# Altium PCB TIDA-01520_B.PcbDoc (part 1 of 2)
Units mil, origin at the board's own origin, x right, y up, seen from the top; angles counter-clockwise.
Board outline 2952.76 x 2362.2 mil, 2 copper layers (Top Layer, Bottom Layer), stack 62 mil thick; 118 components, 52 nets, 283 pads, 133 vias.
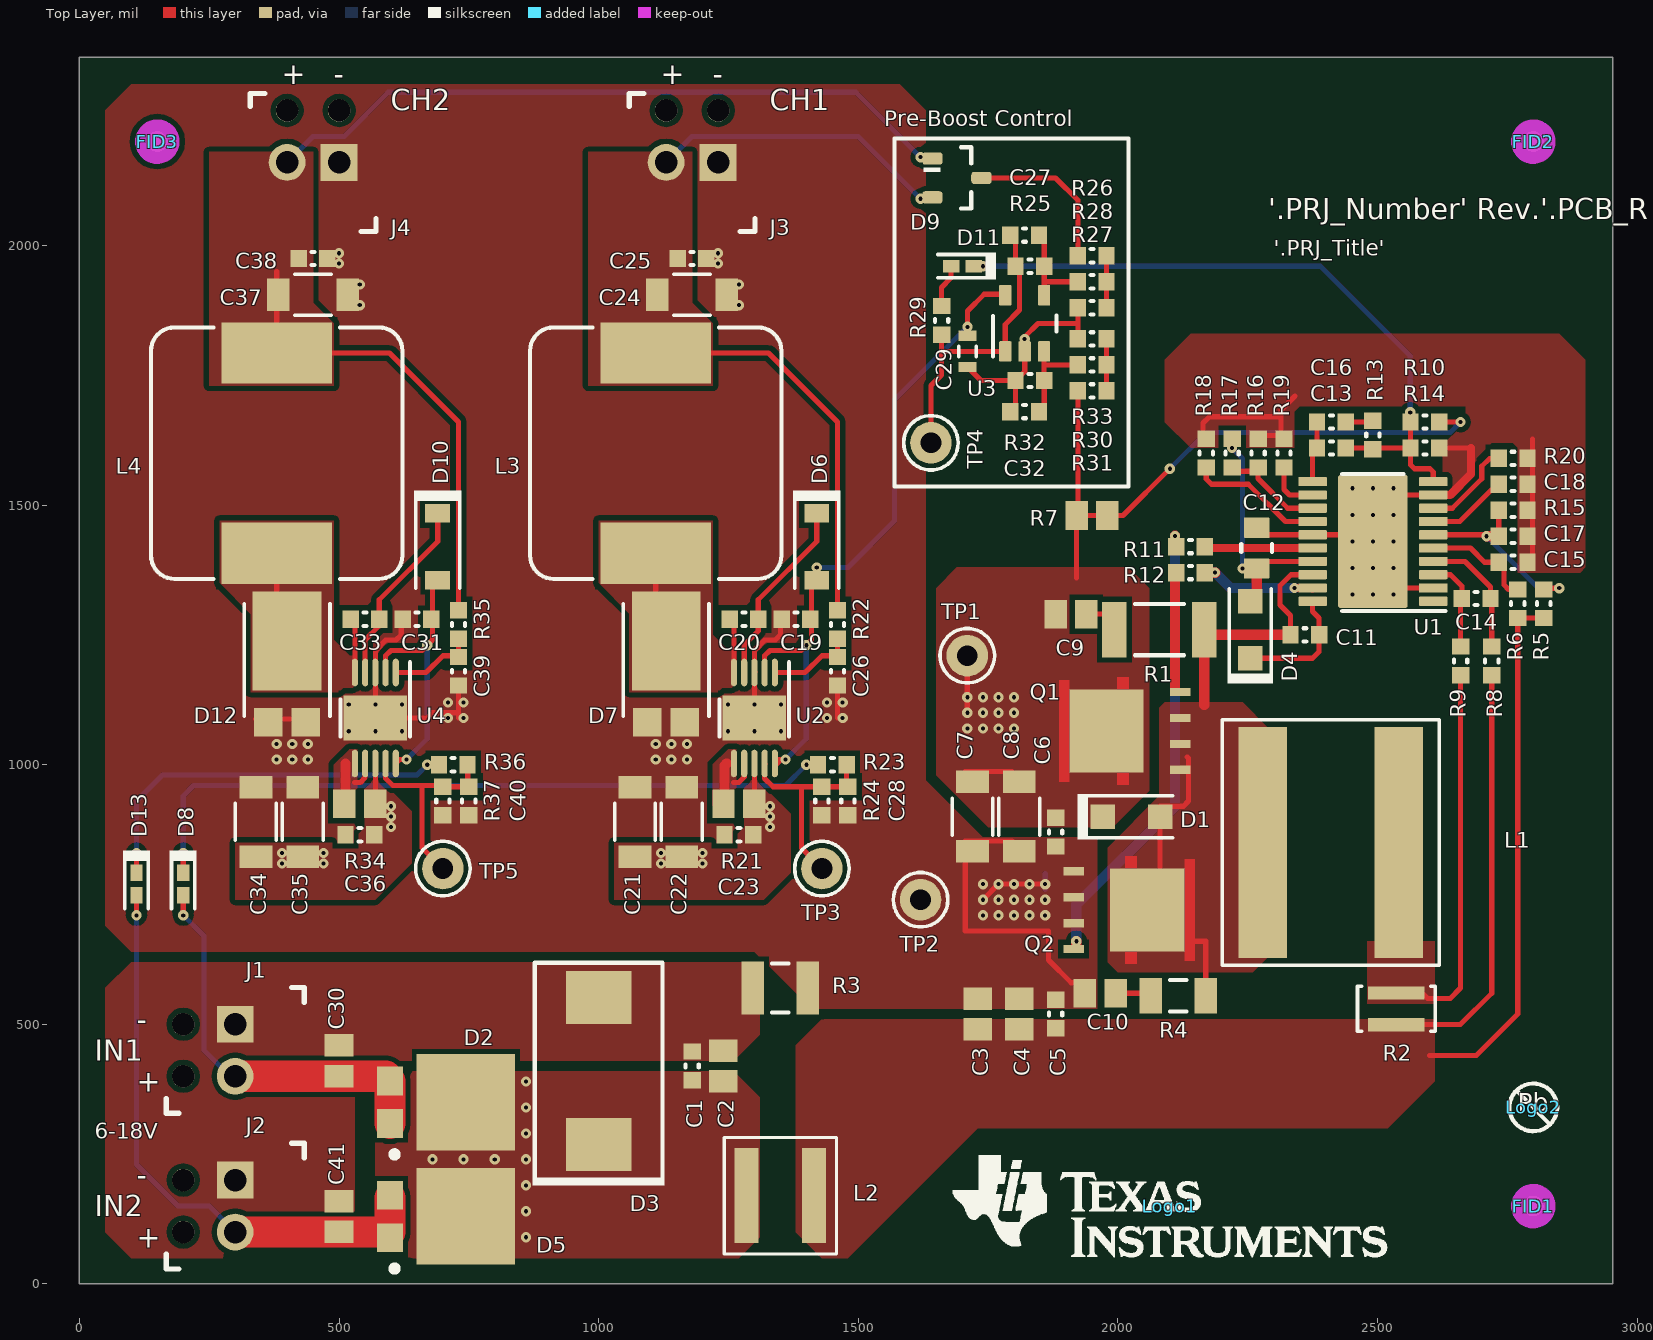
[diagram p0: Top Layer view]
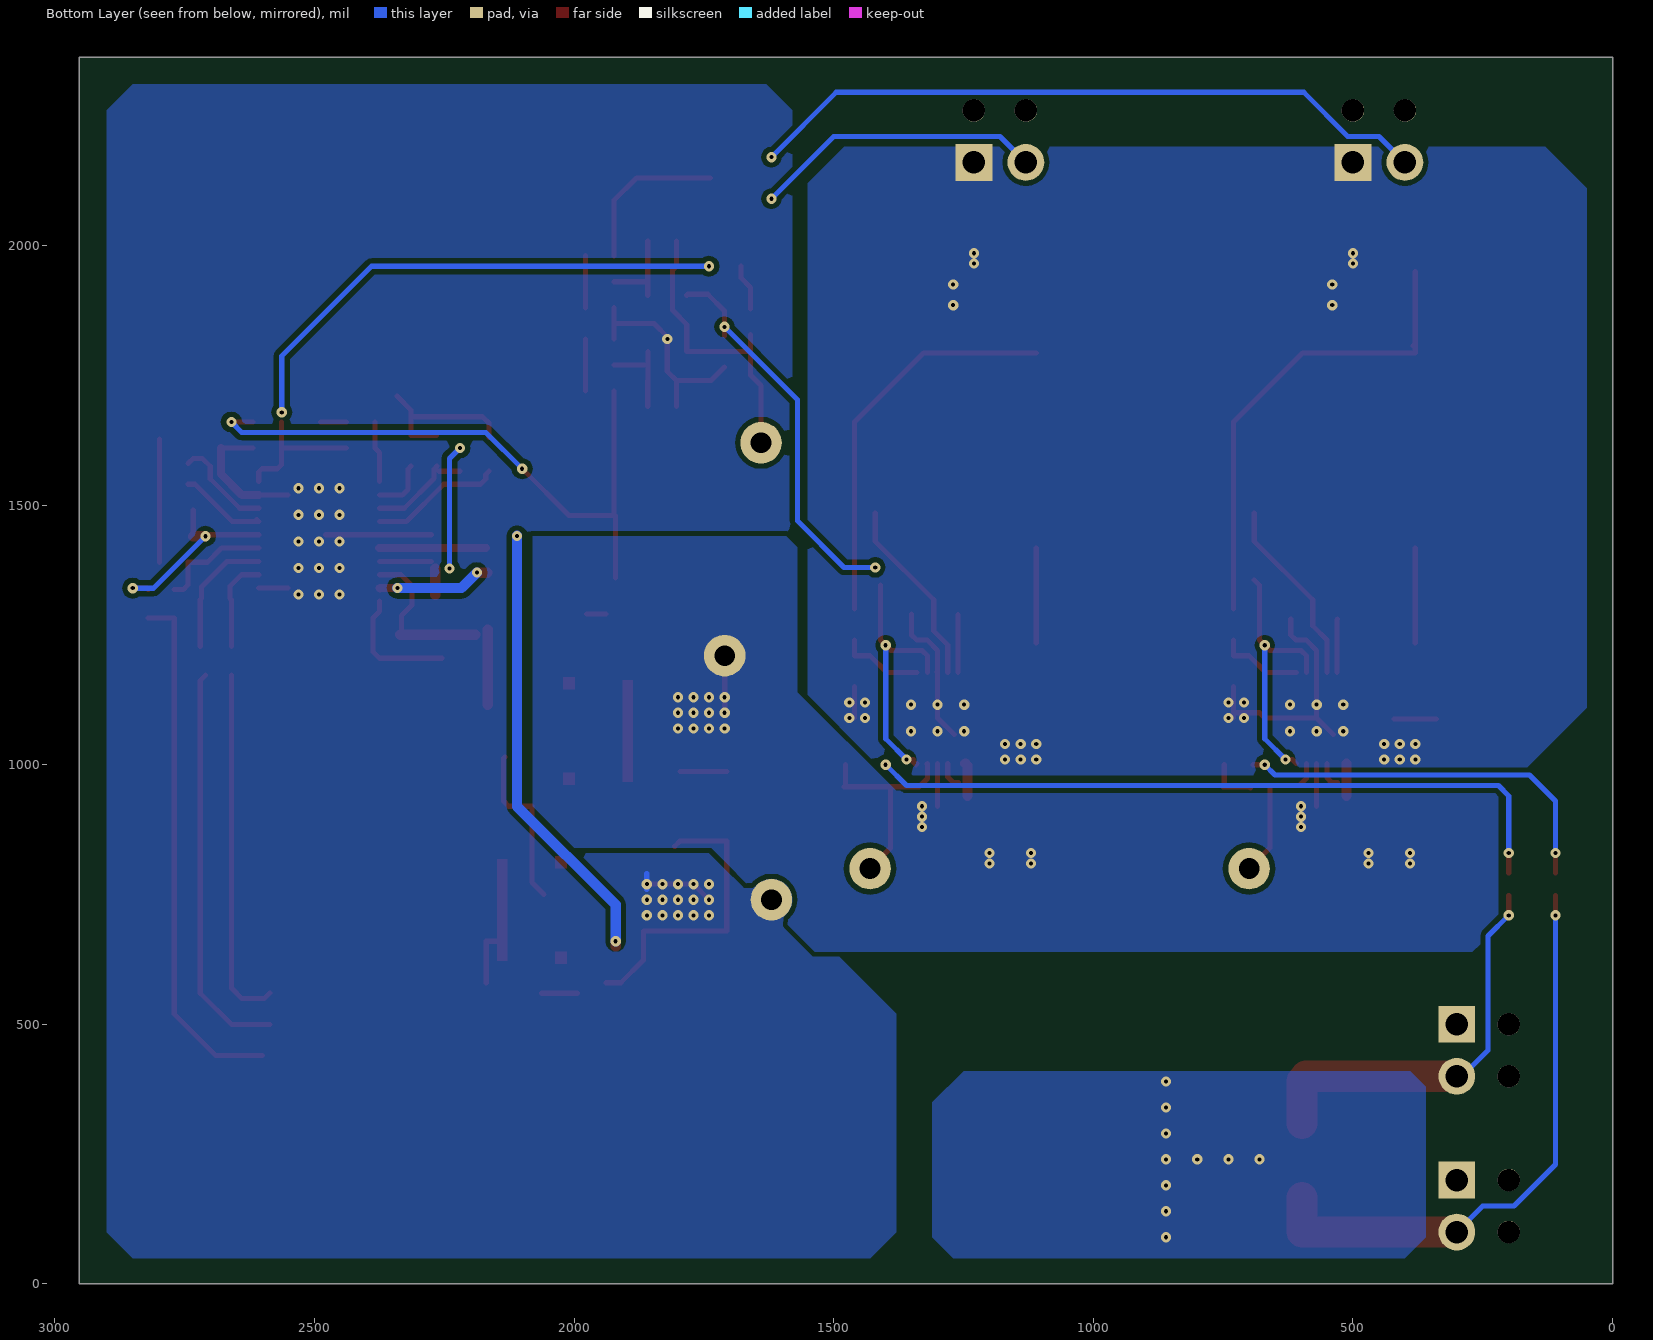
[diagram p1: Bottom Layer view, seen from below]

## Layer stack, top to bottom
Top Solder: solder mask 0.4, Solder Resist, Dk 3.5
Top Layer: signal copper 1.4
Dielectric1: core 59.2, FR-4, Dk 4.8
Bottom Layer: signal copper 1.4
Bottom Solder: solder mask 0.4, Solder Resist, Dk 3.5

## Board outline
0,0 2952.76,0 2952.76,2362.2 0,2362.2

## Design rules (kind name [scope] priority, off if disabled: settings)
AcuteAngle [All] p1: minimum=4.50000000000000E+0001 checktracksonly=FALSE
AssemblyTestPointUsage [All] p1: valid=2
BoardOutlineClearance BoardOutlineClearance_MountingHoles [OnCopper and InComponentClass('Mounting Holes')] p1: gap=40
BoardOutlineClearance BoardOutlineClearance_Poly [OnCopper and IsPoly] p2: gap=25
BoardOutlineClearance [OnCopper and Not InComponentClass('Logo') and not InComponentClass('FiducialMark') and not InRegion(1000,500,4000,800) and not InPoly] p3: gap=35
Clearance Clearance_Keepouts [((IsTrack Or IsArc) And Not InPoly) And IsFree and IsKeepOut vs ((IsTrack Or IsArc) And Not InPoly) And IsFree and IsKeepOut] p1: gap=0
Clearance Clearance_Poly [InPolygon] p2: gap=10
Clearance [All] p3: gap=7.87
ComponentClearance ComponentClearance_MountingHoles_FiducialMarks [InComponentClass('Mounting Holes') vs InComponentClass('FiducialMark')] p1: gap=50 collisioncheckmode=3 verticalgap=10 showdistances=FALSE
ComponentClearance ComponentClearance_Shunt [InComponentClass('Header') vs InComponentClass('Shunt')] p2: gap=0 collisioncheckmode=3 verticalgap=0 showdistances=FALSE
ComponentClearance ComponentClearance_Logo [InComponentClass('Logo')] p3: gap=50 collisioncheckmode=3 verticalgap=10 showdistances=FALSE
ComponentClearance ComponentClearance_ScrewToNut [(HasFootprint('NY PMS 440 0025 PH')) vs (HasFootprint('Keystone_1902C'))] p4: gap=5 collisioncheckmode=3 verticalgap=10 showdistances=FALSE
ComponentClearance ComponentClearance_MountingHoles [InComponentClass('Mounting Holes')] p5: gap=180 collisioncheckmode=3 verticalgap=100000 showdistances=FALSE
ComponentClearance ComponentClearance_SmallPassives [HasFootprint('0201*') or HasFootprint('0402*') or HasFootprint('0508') or HasFootprint('0603*') or HasFootprint('0612') or HasFootprint('0805*') or HasFootprint('0815*') or HasFootprint('0830*') or HasFootprint('1206*') or HasFootprint('1210*') or HasFootprint('1808*') or HasFootprint('1812*') or HasFootprint('1825*') or HasFootprint('2010*') or HasFootprint('2220*') or HasFootprint('2225*') or HasFootprint('2512*') or HasFootprint('2728*') or HasFootprint('3518*') vs HasFootprint('0201*') or HasFootprint('0402*') or HasFootprint('0508') or HasFootprint('0603*') or HasFootprint('0612') or HasFootprint('0805*') or HasFootprint('0815*') or HasFootprint('0830*') or HasFootprint('1206*') or HasFootprint('1210*') or HasFootprint('1808*') or HasFootprint('1812*') or HasFootprint('1825*') or HasFootprint('2010*') or HasFootprint('2220*') or HasFootprint('2225*') or HasFootprint('2512*') or HasFootprint('2728*') or HasFootprint('3518*')] p6: gap=12 collisioncheckmode=3 verticalgap=10 showdistances=FALSE
ComponentClearance ComponentClearance_THtoSMT [IsThruComponent vs IsSMTComponent] p7: gap=40 collisioncheckmode=3 verticalgap=30 showdistances=FALSE
ComponentClearance ComponentClearance_THtoTH [IsThruComponent vs IsThruComponent] p8: gap=30 collisioncheckmode=3 verticalgap=30 showdistances=FALSE
ComponentClearance [All] p9: gap=30 collisioncheckmode=3 verticalgap=10 showdistances=FALSE
DiffPairsRouting [All] p1: maxlimit=100 minlimit=10 mostfreqgap=10 toplayer_minwidth=15 toplayer_maxwidth=15 toplayer_prefwidth=15 bottomlayer_minwidth=15 bottomlayer_maxwidth=15 bottomlayer_prefwidth=15 maxuncoupledlength=1000
FabricationTestPointUsage TestPointUsage [All] p1: valid=2 allowmultiple=FALSE
FabricationTestpoint Testpoint [All] p1: side=3 testpointundercomponent=TRUE minsize=40 maxsize=100 preferedsize=60 minholesize=0 maxholesize=40 preferedholesize=32 testpointgrid=1 allowsidetop=TRUE allowsidebottom=TRUE usegrid=TRUE gridtolerance=0.01
FanoutControl Fanout_LCC [IsLCC] p1: bgadir=Out bgaviamode=Centered fanoutstyle=Auto fanoutdirection=Alternating viagrid=1 // Fanout_LCC (Default Rule)
FanoutControl Fanout_BGA [IsBGA] p2: bgadir=Out bgaviamode=Centered fanoutstyle=Auto fanoutdirection=Alternating viagrid=1 // Fanout_BGA (Default Rule)
FanoutControl Fanout_Default [All] p4: bgadir=Out bgaviamode=Centered fanoutstyle=Auto fanoutdirection=Alternating viagrid=1 // Fanout_Default (Default Rule)
FanoutControl Fanout_Small [(CompPinCount < 5)] p5: bgadir=Out bgaviamode=Centered fanoutstyle=Auto fanoutdirection=OutThenIn viagrid=1 // Fanout_Small (Default Rule)
HoleSize [All] p1: absolutevalues=TRUE maxlimit=251 minlimit=7.87 maxpercent=80.000 minpercent=20.000
MinimumAnnularRing MinimumAnnularRing_ThermalPadVias [IsVia and InAnyComponent] p1: minimumring=5.91
MinimumAnnularRing [All] p2: minimumring=5.91
MinimumSolderMaskSliver MinimumSolderMaskSliver_Logo [InComponentClass('Logo') vs InComponentClass('Logo')] p1: minsoldermaskwidth=0.7
MinimumSolderMaskSliver [All] p2: minsoldermaskwidth=3.94
PlaneConnect [All] p1: planeconnectstyle=Relief reliefexpansion=10 reliefentries=4 reliefconductorwidth=10 reliefairgap=10
PolygonConnect [All] p1: connectstyle=Direct reliefconductorwidth=10 reliefentries=4 polygonreliefangle="90 Angle" airgapwidth=10
RoutingVias ThermalPadVias [IsVia and InAnyComponent] p1: holewidth=7.87 width=19.68 viastyle="Through Hole" minholewidth=7.87 minwidth=19.68 maxholewidth=12.99 maxwidth=23.62
RoutingVias [All] p2: holewidth=16 width=34 viastyle="Through Hole" minholewidth=7.87 minwidth=19.68 maxholewidth=40 maxwidth=65
SilkToBoardRegionClearance [Not ((IsComment or IsDesignator) And (Hide <> 'False')) and not InRegion(1000,500,4000,800)] p1:
SilkToSilkClearance SilkToSilkClearance_Pb-FreeLogo [(HasFootprint('Pb-Free_Overlay_Medium') OR HasFootprint('Pb-Free_Overlay_Small')) vs (HasFootprint('Pb-Free_Overlay_Medium') OR HasFootprint('Pb-Free_Overlay_Small'))] p1: silktosilkclearance=0
SilkToSilkClearance [All] p2: silktosilkclearance=4
SilkToSolderMaskClearance SilkToSolderMaskClearance_D4 [InComponent('D4') or InComponent('D1')  or InComponent('D2') or InComponent('D8') or InComponent('D13') or InComponent('D3')] p1: minsilkscreentomaskgap=3.29 clearancetoexposedcopper=TRUE
SilkToSolderMaskClearance SilkToComponentPadClearance [(IsPad or IsFill or IsRegion) and InAnycomponent] p2: minsilkscreentomaskgap=5 clearancetoexposedcopper=TRUE
SilkToSolderMaskClearance "Silk to Solder Mask Opening" [All] p3: minsilkscreentomaskgap=4 clearancetoexposedcopper=FALSE
SolderMaskExpansion [All] p1: expansion=1.97
Width [All] p1: maxlimit=100 minlimit=6 preferedwidth=10 checkconnectedcopper=TRUE
15 further rules are at their usual default settings.

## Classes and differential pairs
component class Logo: Logo1
component class TIDA-01520_B_Hardware: FID1 FID2 FID3 Logo1 Logo2 ZZ1 ZZ2 ZZ3
component class FiducialMark: FID1 FID2 FID3
component class AssemblyNote: ZZ1 ZZ2 ZZ3
component class TIDA-01520_B: C1 C2 C3 C4 C5 C6 C7 C8 C9 C10 C11 C12 C13 C14 C15 C16 C17 C18 C19 C20 C21 C22 C23 C24 C25 C26 C27 C28 C29 C30 C31 C32 C33 C34 C35 C36 C37 C38 C39 C40 C41 D1 D2 D3 D4 D5 D6 D7 D8 D9 D10 D11 D12 D13 J1 J2 J3 J4 L1 L2 L3 L4 L22 Q1 Q2 R1 R2 R3 R4 R5 R6 R7 R8 R9 R10 R11 R12 R13 R14 R15 R16 R17 R18 R19 R20 R21 R22 R23 R24 R25 R26 R27 R28 R29 R30 R31 R32 R33 R34 R35 R36 R37 TP1 TP2 TP3 TP4 TP5 U1 U2 U3 U4

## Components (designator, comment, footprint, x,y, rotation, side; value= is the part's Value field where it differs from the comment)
C1 "CGA3E2X7R1H104K080AA" 0603L 1180,420 r90 top
C2 "CGA4J3X5R1H475M125AB" 0805L 1240,420 r90 top
C3 "CGA4J3X5R1H475M125AB" 0805L 1730,520 r90 top
C4 "CGA4J3X5R1H475M125AB" 0805L 1810,520 r90 top
C5 "CGA3E2X7R2A102K080AA" 0603L 1880,520 r90 top
C6 "CGA3E3X7S2A104K080AB" 0603L 1880,870 r270 top
C7 "CGA5L3X7S2A225K160AB" 1206_180 1720,900 r270 top
C8 "CGA5L3X7S2A225K160AB" 1206_180 1810,900 r270 top
C9 "GRM216R71E681KA01D" 0805L 1909.53,1290 r0 top
C10 "GRM2165C2A681JA01D" 0805L 1966.14,560 r180 top
C11 "CGA3E2X7R1H104K080AA" 0603L 2360,1250 r180 top
C12 "GCM21BR71C475KA73L" 0805_HV1 2267.14,1417.2 r270 top
C13 "CGA3E2X7R2A102K080AA" 0603L 2411.14,1610 r0 top
C14 "CGA3E2NP01H101J080AA" 0603L 2690,1320 r180 top
C15 "CGA3E3X7R1H474K080AE" 0603L 2761.14,1390 r0 top
C16 "CGA3E2X7R1H104K080AA" 0603L 2411.14,1660 r0 top
C17 "CGA3E2NP01H101J080AA" 0603L 2761.14,1440 r0 top
C18 "CGA3E3X8R1E224K080AB" 0603L 2761.14,1540 r0 top
C19 "GRM188R60J106ME84" 0603L 1380,1280 r180 top
C20 "CGA3E1X7R1V105K080AC" 0603L 1280,1280 r180 top
C21 "CGA5L3X7S2A225K160AB" 1206_180 1070,890 r90 top
C22 "CGA5L3X7S2A225K160AB" 1206_180 1160,890 r90 top
C23 "CGA3E3X7S2A104K080AB" 0603L 1270,865 r180 top
C24 "CGA5L3X7S2A225K160AB" 1206_180 1180,1905 r0 top
C25 "CGA3E3X7S2A104K080AB" 0603L 1180,1975 r0 top
C26 "GRM1885C1H471JA01D" 0603L 1460,1180 r270 top
C27 "CGA3E2X7R1H473K080AA" 0603L 1820.47,2020 r0 top
C28 "CGA3E2X7R1H104K080AA" 0603L 1480,930 r270 top
C29 "CGA3E2X7R1H104K080AA" 0603S 1710.47,1795.86 r270 top
C30 "CGA4J3X5R1H475M125AB" 0805L 500,430 r90 top
C31 "GRM188R60J106ME84" 0603L 650,1280 r180 top
C32 "CGA3E2X7R1H473K080AA" 0603L 1820.47,1680 r180 top
C33 "CGA3E1X7R1V105K080AC" 0603L 550,1280 r180 top
C34 "CGA5L3X7S2A225K160AB" 1206_180 340,890 r90 top
C35 "CGA5L3X7S2A225K160AB" 1206_180 430,890 r90 top
C36 "CGA3E3X7S2A104K080AB" 0603L 540,865 r180 top
C37 "CGA5L3X7S2A225K160AB" 1206_180 450,1905 r0 top
C38 "CGA3E3X7S2A104K080AB" 0603L 450,1975 r0 top
C39 "GRM1885C1H471JA01D" 0603L 730,1180 r270 top
C40 "CGA3E2X7R1H104K080AA" 0603L 750,930 r270 top
C41 "CGA4J3X5R1H475M125AB" 0805L 500,130 r90 top
D1 "PMEG6010CEH,115" SOD-123F 2026.14,900 r0 top
D2 "V12P10-M3/86A" TO-277A 670,350 r90 top
D3 "TPSMD26A" SMC_265 1000,410 r90 top
D4 "PMEG6010CEH,115" SOD-123F 2255,1260 r90 top
D5 "V12P10-M3/86A" TO-277A 670,130 r90 top
D6 "MMSD4148T1G" SOD-123 1420,1420 r270 top
D7 "PDS3100Q-13" PowerDI5 1130,1160 r90 top
D8 "RB520S30,115" SOD-523 200,770 r270 top
D9 "BAS70-05-7-F" SOT-23 1690,2130 r0 top
D10 "MMSD4148T1G" SOD-123 690,1420 r270 top
D11 "RB520S30,115" SOD-523 1700.47,1960 r180 top
D12 "PDS3100Q-13" PowerDI5 400,1160 r90 top
D13 "RB520S30,115" SOD-523 110,770 r270 top
FID1 "Fiducial" Fiducial10-20 2800,150 r180 top
FID2 "Fiducial" Fiducial10-20 2800,2200 r180 top
FID3 "Fiducial" Fiducial10-20 150,2200 r180 top
J1 "1725656" CONN_1725656 300,450 r270 top
J2 "1725656" CONN_1725656 300,150 r270 top
J3 "1725656" CONN_1725656 1180,2160 r180 top
J4 "1725656" CONN_1725656 450,2160 r180 top
L1 "XAL1010-153MEB" XAL1010 2410,850 r180 top
L2 "XAL5030-222MEB" XAL5030 1350,170 r0 top
L3 "784771470" WE-PDA_1260 1110,1600 r180 top
L4 "784771470" WE-PDA_1260 380,1600 r180 top
Logo1 "Texas Instruments" TI_Stacked_Overlay_Small 2100,150 r0 top
Logo2 "Pb-Free Symbol" Pb-Free_Overlay_Small 2800,340 r0 top
Q1 "SQJA60EP" PowerPAK_SO-8L 2010,1065 r180 top
Q2 "SQJA60EP" PowerPAK_SO-8L 2025,720 r0 top
R1 "CRCW20106R80JNEF" 2010L 2080,1260 r180 top
R2 "PRL1632-R006-F-T1" 0612 2536.14,530 r90 top
R3 "CRCW12100000Z0EA" 1210L 1350,570 r0 top
R4 "PHP01206E10R0BST5" 1206L 2116.14,555 r0 top
R5 "CRCW0603100KJNEA" 0603L 2820,1310 r270 top
R6 "CRCW06033R30JNEA" 0603L 2770,1310 r270 top
R7 "CRCW080549R9FKEA" 0805L 1950,1480 r180 top
R8 "CRCW06031K00FKEA" 0603L 2720,1200 r270 top
R9 "CRCW06031K00FKEA" 0603L 2660,1200 r270 top
R10 "CRCW0603100KFKEA" 0603L 2591.14,1660 r0 top
R11 "CRCW060330R0JNEA" 0603L 2140,1420 r180 top
R12 "CRCW06030000Z0EA" 0603L 2140,1370 r180 top
R13 "CRCW06031K00FKEA" 0603L 2491.14,1635 r90 top
R14 "CRCW06032K74FKEA" 0603L 2591.14,1610 r0 top
R15 "CRCW060322K0JNEA" 0603L 2761.14,1490 r180 top
R16 "CRCW06030000Z0EA" 0603L 2270,1600 r90 top
R17 "CRCW06030000Z0EA" 0603L 2220,1600 r90 top
R18 "CRCW06030000Z0EA" 0603L 2170,1600 r270 top
R19 "CRCW060349K9FKEA" 0603L 2320,1600 r270 top
R20 "RC0603FR-0727KL" 0603L 2761.14,1590 r180 top
R21 "ERJ-6RQFR22V" 0805L 1270,925 r0 top
R22 "CRCW060310K0FKEA" 0603L 1460,1270 r90 top
R23 "CRCW06032K00FKEA" 0603L 1450,1000 r180 top
R24 "CRCW0603330RJNEA" 0603L 1430,930 r270 top
R25 "CRCW0603300KFKEA" 0603L 1830.47,1960 r180 top
R26 "RC0603FR-0718KL" 0603L 1950.47,1980 r180 top
R27 "CRCW06032K00FKEA" 0603L 1950.47,1880 r0 top
R28 "CRCW060310K0FKEA" 0603L 1950.47,1930 r180 top
R29 "CRCW060313K3FKEA" 0603L 1660.47,1855.86 r90 top
R30 "CRCW060310K0FKEA" 0603L 1950.47,1770 r180 top
R31 "RC0603FR-0722KL" 0603L 1950.47,1720 r180 top
R32 "CRCW0603300KFKEA" 0603L 1830.47,1740 r0 top
R33 "CRCW06032K00FKEA" 0603L 1950.47,1820 r0 top
R34 "ERJ-6RQFR22V" 0805L 540,925 r0 top
R35 "CRCW060310K0FKEA" 0603L 730,1270 r90 top
R36 "CRCW06032K00FKEA" 0603L 720,1000 r180 top
R37 "CRCW0603330RJNEA" 0603L 700,930 r270 top
TP1 "5001" Keystone5001 1710,1210 r90 top
TP2 "5001" Keystone5001 1620,740 r90 top
TP3 "5001" Keystone5001 1430,800 r90 top
TP4 "5001" Keystone5001 1640,1620 r90 top
TP5 "5001" Keystone5001 700,800 r90 top
U1 "LM5122QMHX/NOPB" PWP0020A_N 2491.14,1430 r180 top
U2 "TPS92515HVQDGQRQ1" DGQ0010E_N 1300,1090 r270 top
U3 "OPA348AQDBVRQ1" DBV0005A_N 1820.47,1850 r90 top
U4 "TPS92515HVQDGQRQ1" DGQ0010E_N 570,1090 r270 top
ZZ1 "These assemblies are ESD sensitive, ESD precautions shall be observed." AssemblyNote 0,2760 r0 top
ZZ2 "These assemblies must be clean and free from flux and all contaminants. Use of no clean flux is not acceptable." AssemblyNote 0,2662.2 r0 top
ZZ3 "These assemblies must comply with workmanship standards IPC-A-610 Class 2, unless otherwise specified." AssemblyNote 0,2562.2 r0 top

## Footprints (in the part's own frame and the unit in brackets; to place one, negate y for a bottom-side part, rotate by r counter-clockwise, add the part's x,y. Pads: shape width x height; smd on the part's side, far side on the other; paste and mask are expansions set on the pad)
0603L [mm] "0603 from SM-752 data"
  rect 0.8x0.85 smd: 1(-0.7,0) 2(0.7,0)
  silkscreen extent -0.07,-0.33 0.07,0.33, body extent -0.87,-0.47 0.87,0.47, height 1
0603S [mil]
  rect 20x35 smd: 1(-30,0) 2(30,0)
  silkscreen extent -10,-17 10,17, body extent -34,-19 34,19, height 39
0612 [mm] "Panasonic recommended land pattern, fb97d03ed01.pdf dated April 2008"
  rect 0.65x2.75 smd: 1(-0.775,0) 2(0.775,0)
  silkscreen extent -1.1,-1.9 1.1,1.9, body extent -0.9,-1.7 0.9,1.7, height 0.85
0805_HV1 [mm] "Custom footprint based on analyzing multiple manufacturer recommendations"
  rrect10% 1x1.25 smd: 1(-1,0) 2(1,0)
  silkscreen extent -0.2,-0.75 0.2,0.75, body extent -1.1,-0.72 1.1,0.73, height 1.45
0805L [mm] "0805 from SM-752 data"
  rect 1.1x1.4 smd: 1(-0.75,0) 2(0.75,0)
  body extent -1.1,-0.72 1.1,0.72, height 1.45
1206_180 [mm] "1206_180"
  rect 1.1x1.6 smd: 1(-1.7,0) 2(1.7,0)
  silkscreen extent -0.9,-1 0.9,1, body extent -1.75,-0.95 1.75,0.95, height 1.8
1206L [mm] "1206 from SM-752 data"
  rect 1.1x1.75 smd: 1(-1.35,0) 2(1.35,0)
  silkscreen extent -0.4,-0.77 0.4,0.77, body extent -1.7,-0.9 1.7,0.9, height 1.35
1210L [mm] "1210 from SM-752 data"
  rect 1.1x2.6 smd: 1(-1.35,0) 2(1.35,0)
  silkscreen extent -0.4,-1.2 0.4,1.2, body extent -1.7,-1.35 1.7,1.35, height 1.35
2010L [mm] "1206 from SM-752 data"
  rect 1.2x2.7 smd: 1(-2.2,0) 2(2.2,0)
  silkscreen extent -1.2,-1.25 1.2,1.25, body extent -2.73,-1.45 2.73,1.45, height 1.66
AssemblyNote [mil] "Assembly Note"
CONN_1725656 [mm] "Phoenix Contact"
  rect 1.8x1.8 hole 1.1: 1(-1.27,0)
  round 1.8 hole 1.1: 2(1.27,0)
  round 1.1 hole 1.1 unplated: MH1(-1.275,-2.54) MH2(1.27,-2.54)
  silkscreen extent -3.08,-3.37 3.08,3.37, body extent -2.77,-3.1 2.77,3.1, height 8.52
DBV0005A_N [mm] "SOT23, 5-Leads, Body 2.9x1.6mm, Pitch 0.95mm, Lead Span 2.8mm, IPC Medium Density"
  rrect17% 1x0.6 smd: 1(-1.375,0.95) 2(-1.375,0) 3(-1.375,-0.95) 4(1.375,-0.95) 5(1.375,0.95)
  silkscreen extent -1.63,-1.55 0.38,1.55, body extent -1.42,-1.46 1.42,1.46, height 1.09
DGQ0010E_N [mm] "TSSOP, 10-Leads, Body 3x3mm, Pitch 0.5mm, Thermal Pad 1.83x2.1mm, IPC Medium Density"
  rrect5% 1.83x2.1 on Top Paste: 0(0,0)
  rrect5% 1.83x2.1 on Top Solder: 0(0,0)
  rrect100% 1.35x0.3 smd: 1(-2.225,1) 2(-2.225,0.5) 3(-2.225,0) 4(-2.225,-0.5) 5(-2.225,-1) 6(2.225,-1) 7(2.225,-0.5) 8(2.225,0) 9(2.225,0.5) 10(2.225,1)
  rect 2.2x3.1 smd paste-1.1 mask-1.1: 11(0,0)
  silkscreen extent -2.73,-1.7 0.9,1.7, body extent -2.46,-1.5 2.46,1.5, height 0.95
Fiducial10-20 [mm]
  round 1 smd mask+0.5: 1(0,0)
  Top Layer keep-out circle w1.178: c0,0 r0.5
Keystone5001 [mil] "For Keystone 500x miniature loop terminals"
  round 80 hole 40: 1(0,0)
  silkscreen extent -52,-52 52,52, body extent -49,-49 49,49, height 182
Pb-Free_Overlay_Small [mil]
  silkscreen extent -46,-46 46,46
PowerDI5 [mm] "Diodes Inc recommended land pattern, ap02001.pdf rev 60"
  rect 1.4x1.39 smd: 1(-1.991,0.92) 2(-1.991,-0.92)
  rect 4.86x3.36 smd: 3(1.991,0)
  silkscreen extent -1.7,-2.1 3.8,2.1, body extent -2.27,-2.03 4.33,2.03, height 1.17
PowerPAK_SO-8L [mm] "based on Vishay recommended land pattern Document 63818 Feb 7, 2012"
  rect 1x0.41 smd: 1(-2.805,1.905) 2(-2.805,0.635) 3(-2.805,-0.635) 4(-2.805,-1.905)
  rect 3.63x4.061 smd: 5(0.805,0)
  Top Layer region: 2.615,-2.5 3.125,-2.5 3.125,2.5 2.615,2.5
  Top Layer region: -0.298,2.03 0.298,2.03 0.298,2.64 -0.298,2.64
  Top Layer region: -0.298,-2.64 0.298,-2.64 0.298,-2.03 -0.298,-2.03
  body extent -3.07,-2.57 3.08,2.57, height 1.21
PWP0020A_N [mm] "TSOP, 20-Leads, Body 6.5x4.4mm, Pitch 0.65mm, Exposed Pad, IPC Medium Density"
  rrect22% 1.4x0.45 smd: 1(-2.95,2.925) 2(-2.95,2.275) 3(-2.95,1.625) 4(-2.95,0.975) 5(-2.95,0.325) 6(-2.95,-0.325) 7(-2.95,-0.975) 8(-2.95,-1.625) 9(-2.95,-2.275) 10(-2.95,-2.925) 11(2.95,-2.925) 12(2.95,-2.275) 13(2.95,-1.625) 14(2.95,-0.975) 15(2.95,-0.325) 16(2.95,0.325) 17(2.95,0.975) 18(2.95,1.625) 19(2.95,2.275) 20(2.95,2.925)
  rrect6% 3.4x6.5 smd paste-2 mask-2: 21(0,0)
  rrect3% 3.15x4.35 on Top Paste: 21(0,0)
  rrect3% 3.15x4.35 on Top Solder: 21(0,0)
  silkscreen extent -3.55,-3.3 1.5,3.4, body extent -3.21,-3.25 3.21,3.25, height 1
SMC_265 [mm] "SMD, 2-Leads, Body 7.15x6.25mm"
  rect 2.6x3.2 smd: 1(-3.6,0) 2(3.6,0)
  silkscreen extent -5.6,-3.22 5.3,3.22, body extent -4.07,-3.13 4.07,3.13, height 2.65
SOD-123 [mm] "On Semi recommended land pattern"
  rect 0.915x1.22 smd: 1(-1.637,0) 2(1.637,0)
  silkscreen extent -2.74,-1.17 2.03,1.17, body extent -1.93,-0.9 1.93,0.9, height 1.35
SOD-123F [mm] "NXP recommended land pattern"
  rect 1.2x1.2 smd paste-0.05: 1(-1.4,0) 2(1.4,0)
  silkscreen extent -2.64,-1.12 2.01,1.12, body extent -1.8,-0.85 1.8,0.85, height 1.2
SOD-523 [mm] "NXP Semiconductor recommended land pattern, nominal STEP model"
  rect 0.8x0.6 smd paste-0.05: 1(-0.55,0) 2(0.55,0)
  silkscreen extent -1.65,-0.66 1.2,0.66, body extent -0.8,-0.4 0.8,0.4, height 0.72
SOT-23 [mm] "SOT23, 3-Leads, Body 2.9x1.3mm, Pitch 0.95mm, Lead Span 2.5mm, IPC Medium Density"
  rrect50% 1x0.6 smd: 1(-1.2,0.95) 2(-1.2,-0.95) 3(1.2,0)
  silkscreen extent -1.62,-1.5 0.7,1.5, body extent -1.16,-1.45 1.21,1.45, height 1
TI_Stacked_Overlay_Small [mil]
  silkscreen extent -418,-98 418,98
TO-277A [mm] "Vishay"
  rect 1.4x1.27 smd: 1(-1.04,1.83) 2(1.04,1.83)
  rect 4.72x4.8 smd: 3(0,-1.883)
  silkscreen extent -2.7,1.45 -2.4,1.75, body extent -2.35,-4.2 2.4,2.45, height 1.2
WE-PDA_1260 [mm] "SMD, 2-Leads, Body 12x12mm"
  rect 5.4x3 smd: 1(0,4.9) 2(0,-4.9)
  silkscreen extent -6.15,-6.15 6.15,6.15, body extent -6,-6 6,6, height 5.86
XAL1010 [mm] "COILCRAFT"
  rect 2.38x11.31 smd: 1(-3.325,0) 2(3.325,0)
  silkscreen extent -5.3,-6 5.3,6, body extent -5.25,-5.9 5.25,5.9, height 10
XAL5030 [mil] "Coilcraft XAL5030 12/12/11"
  rect 46x183 smd: 1(-65,0) 2(65,0)
  silkscreen extent -108,-112 108,112, body extent -108,-112 108,112, height 122

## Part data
C1 C11 C16 C28 C29 C40: "CAP, CERM, 0.1 µF, 50 V,+/- 10%, X7R, AEC-Q200 Grade 1, 0603"
C2 C3 C4 C30 C41: "CAP, CERM, 4.7 µF, 50 V,+/- 20%, X5R, AEC-Q200 Grade 3, 0805"
C5 C13: "CAP, CERM, 1000 pF, 100 V,+/- 10%, X7R, AEC-Q200 Grade 1, 0603"
C6 C23 C25 C36 C38: "CAP, CERM, 0.1 µF, 100 V,+/- 10%, X7S, AEC-Q200 Grade 1, 0603"
C7 C8 C21 C22 C24 C34 C35 C37: "CAP, CERM, 2.2 µF, 100 V, +/- 10%, X7S, AEC-Q200 Grade 1, 1206"
C9: "CAP, CERM, 680 pF, 25 V,+/- 10%, X7R, 0805"
C10: "CAP, CERM, 680 pF, 100 V,+/- 5%, C0G/NP0, 0805"
C12: "CAP, CERM, 4.7 µF, 16 V, +/- 10%, X7R, AEC-Q200 Grade 1, 0805"
C14 C17: "CAP, CERM, 100 pF, 50 V, +/- 5%, C0G/NP0, AEC-Q200 Grade 0, 0603"
C15: "CAP, CERM, 0.47 µF, 50 V, +/- 10%, X7R, AEC-Q200 Grade 1, 0603"
C18: "CAP, CERM, 0.22 µF, 25 V,+/- 10%, X8R, AEC-Q200 Grade 0, 0603"
C19 C31: "CAP, CERM, 10 µF, 6.3 V,+/- 20%, X5R, 0603"
C20 C33: "CAP, CERM, 1 µF, 35 V,+/- 10%, X7R, AEC-Q200 Grade 1, 0603"
C26 C39: "CAP, CERM, 470 pF, 50 V,+/- 5%, C0G/NP0, 0603"
C27 C32: "CAP, CERM, 0.047 µF, 50 V,+/- 10%, X7R, AEC-Q200 Grade 1, 0603"
D1 D4: "Diode, Schottky, 60 V, 1 A, SOD-123F"
D2 D5: "Diode, Schottky, 100 V, 12 A, AEC-Q101, TO-277A"
D3: "Diode, TVS, Uni, 26 V, 42.1 Vc, AEC-Q101, SMC"
D6 D10: "Diode, Switching, 100 V, 0.2 A, SOD-123"
D7 D12: "Diode, Schottky, 100 V, 3 A, AEC-Q101, PowerDI5"
D8 D11 D13: "Diode, Schottky, 30 V, 0.2 A, SOD-523"
D9: "Diode, Schottky, 70 V, 0.07 A, SOT-23"
FID1 FID2 FID3: "Fiducial mark.  There is nothing to buy or mount."
J1 J2 J3 J4: "Terminal Block, 100mil, 2x1, 6A, 63V, TH"
L1: "Inductor, Shielded, Composite, 15 µH, 13.8 A, 0.02 ohm, SMD"
L2: "Inductor, Shielded, Composite, 2.2 µH, 9.2 A, 0.01 ohm, SMD"
L3 L4: "Inductor, Wirewound, Ferrite, 47 µH, 2.3 A, 0.064 ohm, AEC-Q200 Grade 1, SMD"
Logo1: library part TI_Logo, "Texas Instrument Corporate Signature"
Logo2: library part Pb-Free
Q1 Q2: "MOSFET, N-CH, 60 V, 30 A, AEC-Q101, PowerPAK_SO-8L"
R1: "RES, 6.8, 5%, 0.75 W, AEC-Q200 Grade 0, 2010"
R2: "RES, 0.006, 1%, 1 W, 0612"
R3: "RES, 0, 1%, 0.5 W, AEC-Q200 Grade 0, 1210"
R4: "RES, 10.0, 0.1%, 1 W, 1206"
R5: "RES, 100 k, 5%, 0.1 W, 0603"
R6: "RES, 3.3, 5%, 0.1 W, 0603"
R7: "RES, 49.9, 1%, 0.125 W, 0805"
R8 R9 R13: "RES, 1.00 k, 1%, 0.1 W, 0603"
R10: "RES, 100 k, 1%, 0.1 W, 0603"
R11: "RES, 30, 5%, 0.1 W, 0603"
R12 R16 R17 R18: "RES, 0, 5%, 0.1 W, 0603"
R14: "RES, 2.74 k, 1%, 0.1 W, 0603"
R15: "RES, 22 k, 5%, 0.1 W, 0603"
R19: "RES, 49.9 k, 1%, 0.1 W, 0603"
R20: "RES, 27.0 k, 1%, 0.1 W, 0603"
R21 R34: "RES, 0.22, 1%, 0.125 W, 0805"
R22 R28 R30 R35: "RES, 10.0 k, 1%, 0.1 W, 0603"
R23 R27 R33 R36: "RES, 2.00 k, 1%, 0.1 W, 0603"
R24 R37: "RES, 330, 5%, 0.1 W, 0603"
R25 R32: "RES, 300 k, 1%, 0.1 W, 0603"
R26: "RES, 18.0 k, 1%, 0.1 W, 0603"
R29: "RES, 13.3 k, 1%, 0.1 W, 0603"
R31: "RES, 22.0 k, 1%, 0.1 W, 0603"
TP1 TP2 TP3 TP4 TP5: "Test Point, Miniature, Black, TH"
U1: "Wide Input Synchronous Boost Controller with Multiple Phase Capability, PWP0020A"
U2 U4: "2-A, Buck LED Driver with Integrated N-channel FET, High-Side Current Sense, and Shunt FET PWM Dimming Capability, DGQ0010E (VSSOP-10)"
U3: "Automotive, 1MHz, 45uA, RRIO Single Operational Amplifier, DBV0005A (SOT-23-5)"
ZZ1 ZZ2 ZZ3: library part AssemblyNote

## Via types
v1: diameter 19.68, hole 7.87, Top Layer to Bottom Layer, tented both sides, 124 vias
v2: diameter 19.68, hole 7.87, Top Layer to Bottom Layer, 9 vias

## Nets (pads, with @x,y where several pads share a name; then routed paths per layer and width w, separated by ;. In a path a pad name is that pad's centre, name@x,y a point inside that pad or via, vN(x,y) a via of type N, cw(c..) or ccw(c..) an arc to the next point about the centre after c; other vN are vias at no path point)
+: C32.1 R30.2 R32.2 U3.3 | length 168.8
  Top Layer w10: R32.2@1857.87,1740.16 U3.3@1857.87,1795.86 ; C32.1@1858.03,1690 R32.2@1858.03,1740 ; 1859.86,1770 R30.2@1922.91,1770
-: C27.2 R25.1 R28.2 U3.4 | length 169.5
  Top Layer w10: U3.4@1857.87,1904.13 1858.03,1904.29 1858.03,1930 ; C27.2@1858.03,2008.7 R25.1@1858.03,1960 1858.03,1930 ; R28.2@1922.91,1930 1858.03,1930
BAT_GND: C1.2 C2.2 C30.2 C41.2 D3.2 J1.1 J2.1 R3.1
FB: C13.2 D11.1 R10.1 R13.1 R14.1 U1.10 | length 1277.9
  Top Layer w10: C13.2@2438.7,1610 R14.1@2563.58,1610 ; R10.1@2563.58,1660 R14.1@2563.58,1610 ; U1.10@2607.28,1545.16 2607.28,1563.86 2601.14,1570 2571.14,1570 2563.58,1577.56 R14.1@2563.58,1610
  Bottom Layer w10: v1(1740.47,1960) 2390,1960 2563.09,1786.91 v1(2563.09,1678.68)
GND: C3.2 C4.2 C5.2 C6.2 C7.2 C8.2 C10.2 C12.1 C15.2 C17.2 C18.2 C19.2 C21.2 C22.2 C23.2 C24.2 C25.2 C26.2 C28.2 C29.2 C31.2 C32.2 C34.2 C35.2 C36.2 C37.2 C38.2 C39.2 C40.2 D7.1 D7.2 D12.1 D12.2 J3.1 J4.1 Q2.1 Q2.2 Q2.3 R3.2 R14.2 R15.1 R16.2 R18.1 R19.1 R20.1 R24.2 R27.1 R32.1 R33.1 R37.2 TP2.1 U1.2 U1.9 U1.15 U1.21@2491.14,1430 U2.3 U2.11 U3.2 U4.3 U4.11 | length 3167.8
  Top Layer w10: D12.1@339.06,1087.95 D12.2@420.94,1087.95 ; U4.11@537.95,1057.95 U4.11@570,1090 ; C31.2@620,1280 620,1250 610,1240 590,1240 570,1220 U4.3@570,1177.6 v1(570,1115.59) U4.11@570,1090 ; 730,1090 730,1100 ; C39.2@730,1150 730,1100 ; U2.11@1267.95,1057.95 U2.11@1300,1090 v1(1300,1115.59) U2.3@1300,1177.6 1300.91,1178.5 1300,1179.41 1300,1220 1320,1240 1340,1240 1350,1250 C19.2@1350,1290 ; 1460,1090 C26.2@1460,1150 ; C29.2@1710.47,1765.86 1736.34,1740 R32.1@1802.91,1740 ; v1(1740,740) v1(1770,770) v1(1860,770) ; C32.2@1802.91,1690 R32.1@1802.91,1740 ; C8.2@1806.14,843.07 1796.14,853.07 1706.14,853.07 1706.14,680 1866.14,680 1866.14,623.86 1910,580 C10.2@1938.58,580 ; R33.1@1922.91,1820 1922.91,1850 ; R27.1@1922.91,1880 1922.91,1850 ; R18.1@2163.94,1630.36 2163.94,1657.8 2176.14,1670 2313.94,1670 ; R16.2@2265.43,1634.3 2313.94,1634.3 2313.94,1670 ; C12.1@2274.92,1442.8 U1.15@2375,1442.8 U1.21@2478.35,1442.8 ; 2341.14,1710 2313.94,1682.8 2313.94,1670 ; U1.21@2551.57,1340.43 U1.2@2607.28,1340.43 ; U1.21@2551.57,1519.57 U1.9@2607.28,1519.57 ; R14.2@2618.7,1610 2680,1610 ; C15.2@2798.7,1390 R20.1@2798.7,1590 ; 2798.7,1570 2798.7,1627.44 ; U4.11@570,1090 670,1090 680,1100 730,1100 ; R32.1@1802.91,1740 1820.47,1757.56 U3.2@1820.47,1795.86 1820.47,1824.31 1846.16,1850 1922.91,1850
  Top Layer w16: U1.9@2607.28,1519.57 2640.05,1519.57 2680,1559.52 2680,1610
  Bottom Layer w10: 1860,760 1860,790
  other v1: 1740,710 1770,710 1800,710 1830,710 1860,710 1770,740 1800,740 1830,740 1860,740 1740,770 1800,770 1830,770 380,1010 410,1010 440,1010 1110,1010 1140,1010 1170,1010 380,1040 410,1040 440,1040 1110,1040 1140,1040 1170,1040 518.82,1064.41 570,1064.41 621.18,1064.41 1248.82,1064.41 1300,1064.41 1351.18,1064.41 710,1090 740,1090 1440,1090 1470,1090 518.82,1115.59 621.18,1115.59 1248.82,1115.59 1351.18,1115.59 710,1120 740,1120 1440,1120 1470,1120 2451.77,1327.64 2491.14,1327.64 2530.51,1327.64 2451.77,1532.36 2491.14,1532.36 2530.51,1532.36 1820.47,1820.09 540,1885 1270,1885 540,1925 1270,1925 500,1965 1230,1965 500,1985 1230,1985
  other v2: 2451.77,1378.82 2491.14,1378.82 2530.51,1378.82 2451.77,1430 2491.14,1430 2530.51,1430 2451.77,1481.18 2491.14,1481.18 2530.51,1481.18
NetC1_1: C1.1 C2.1 D2.3 D3.1 D5.3 L2.1
  other v1: 860,90 860,140 860,190 680,240 740,240 800,240 860,240 860,290 860,340 860,390
NetC9_2: C9.2 R1.2 | length 36.8
  Top Layer w10: C9.2@1939.05,1290 R1.2@1975.83,1290
NetC10_1: C10.1 R4.1 | length 69.3
  Top Layer w10: C10.1@1993.7,560 R4.1@2062.99,560
NetC11_1: C11.1 D4.1 U1.20 | length 240.3
  Top Layer w10: D4.1@2255,1204.88 2374.88,1204.88 2387.56,1217.56 C11.1@2387.56,1250 2387.56,1282.44 2375,1295 U1.20@2375,1314.84
NetC13_1: C13.1 C16.1 U1.11 | length 118.4
  Top Layer w10: U1.11@2375,1545.16 2375,1601.42 C13.1@2383.58,1610 C16.1@2383.58,1660
NetC14_1: C14.1 R8.1 U1.4 | length 246.5
  Top Layer w10: U1.4@2607.28,1391.61 2668.39,1391.61 2717.56,1342.44 C14.1@2717.56,1320 2720,1317.56 R8.1@2720,1227.56
NetC14_2: C14.2 R9.1 U1.3 | length 181.6
  Top Layer w10: U1.3@2607.28,1366.02 2640.12,1366.02 2662.44,1343.7 C14.2@2662.44,1320 2660,1317.56 R9.1@2660,1227.56
NetC15_1: C15.1 R6.1 U1.5 | length 221.2
  Top Layer w10: U1.5@2607.28,1417.2 2678.94,1417.2 2706.14,1390 2743.58,1390 2743.58,1346.42 2752.44,1337.56 R6.1@2770,1337.56
NetC16_2: C16.2 R13.2 | length 49.9
  Top Layer w10: C16.2@2438.7,1660 R13.2@2488.58,1660
NetC17_1: C17.1 R5.1 R15.2 U1.6 | length 381.9
  Top Layer w10: U1.6@2607.28,1442.8 2702.8,1442.8 2705.59,1440 v1(2710,1440) ; C17.1@2733.58,1448.03 R15.2@2733.58,1490 ; R5.1@2820,1337.56 2822.44,1340 v1(2850,1340)
  Top Layer w20: v1(2710,1440) C17.1@2733.58,1440
  Bottom Layer w10: v1(2710,1440) 2810,1340 v1(2850,1340)
NetC20_1: C20.1 D6.1 U2.4 | length 364.7
  Top Layer w10: U2.4@1280.32,1177.6 1280.32,1230.32 1307.56,1257.56 1307.56,1317.56 1420,1430 D6.1@1420,1484.47
NetC20_2: C20.2 D7.3 L3.1 U2.5 | length 294.7
  Top Layer w10: D7.3@1110,1234.11 L3.1@1110,1417.09 ; U2.5@1260.63,1177.6 C20.2@1260.63,1289.37
NetC26_1: C26.1 R22.1 U2.1 | length 164.1
  Top Layer w10: U2.1@1339.37,1177.6 1397.6,1177.6 1430,1210 1460,1210 R22.1@1460,1240
NetC27_1: C27.1 R25.2 R29.1 TP4.1 U3.1 | length 563.7
  Top Layer w10: TP4.1@1640,1620 1640,1730 1660.47,1750.47 R29.1@1660.47,1828.3 ; 1663.45,1795.86 U3.1@1783.07,1795.86 1783.07,1848.03 1810.47,1875.43 1810.47,1952.44 R25.2@1802.91,1960 C27.1@1802.91,2008.7
NetC28_1: C28.1 R23.1 R24.1 TP3.1 U2.9 | length 413.9
  Top Layer w10: U2.9@1320.59,1001.5 U2.9@1319.69,1002.4 1319.69,973.7 1335.82,957.56 C28.1@1480,957.56 1477.56,960 R23.1@1477.56,1000 ; 1390.5,957.06 1390.5,839.5 TP3.1@1430,800
NetC33_1: C33.1 D10.1 U4.4 | length 364.7
  Top Layer w10: U4.4@550.32,1177.6 550.32,1240.32 577.56,1267.56 577.56,1317.56 690,1430 D10.1@690,1484.47
NetC33_2: C33.2 D12.3 L4.1 U4.5 | length 285.6
  Top Layer w10: D12.3@380,1234.11 L4.1@380,1417.09 ; C33.2@530,1280 530.63,1279.37 U4.5@530.63,1177.6
NetC39_1: C39.1 R35.1 U4.1 | length 164.1
  Top Layer w10: U4.1@609.37,1177.6 667.6,1177.6 700,1210 730,1210 R35.1@730,1240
